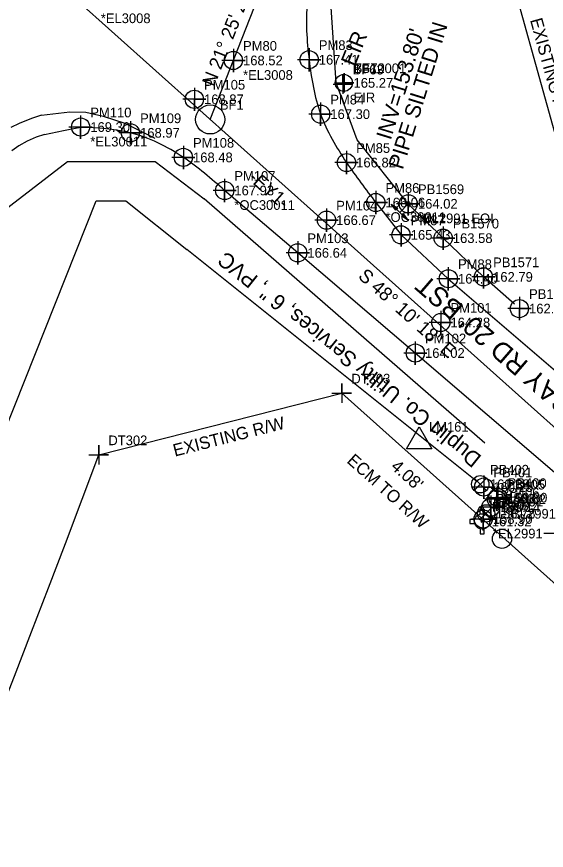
# Model space of a CAD drawing. Extents: x 2262665 to 2270527, y 505476 to 514960.
# Drawn here: x 2266186.8 to 2266323.3, y 509233.9 to 509448.8 of the extents above; entities that cross this region are included whole.
import ezdxf

# ---------------------------------------------------------------- set-up
doc = ezdxf.new("R2010")
doc.units = 0
for name, color, linetype in [('Exist DTM Crownline Cogo Comment', 7, 'Continuous'), ('Exist DTM Crownline Cogo Elevation', 7, 'Continuous'), ('Exist DTM Crownline Cogo Number', 7, 'Continuous'), ('Exist DTM Crownline Cogo Point CELL', 7, 'Continuous'), ('Exist Horizontal Alignment', 7, 'Continuous'), ('Exist Horizontal Alignment Direction Label', 7, 'Continuous'), ('Exist Property Corner CELL', 7, 'Continuous'), ('Exist Property Corner Cogo Number', 7, 'Continuous'), ('Exist Property Iron Pin CELL', 7, 'Continuous'), ('Exist Property Iron Pin Cogo Comment', 7, 'Continuous'), ('Exist Property Iron Pin Cogo Elevation', 7, 'Continuous'), ('Exist Property Iron Pin Cogo Number', 7, 'Continuous'), ('Exist Property Iron Pin Text', 7, 'Continuous'), ('Exist Right of Way Control of Access Line', 7, 'Continuous'), ('Exist Right of Way Line', 7, 'Continuous'), ('Exist Right of Way Line Text', 7, 'Continuous'), ('Exist Right of Way Monument CELL', 7, 'Continuous'), ('Exist Right of Way Monument Cogo Number', 7, 'Continuous'), ('Exist Right of Way Monument Text', 7, 'Continuous'), ('Exist Roads EOP', 7, 'Continuous'), ('Exist Roads EOP Cogo Comment', 7, 'Continuous'), ('Exist Roads EOP Cogo Elevation', 7, 'Continuous'), ('Exist Roads EOP Cogo Number', 7, 'Continuous'), ('Exist Roads EOP Cogo Point CELL', 7, 'Continuous'), ('Exist Roads EOP Text', 7, 'Continuous'), ('Exist Roads EOT', 7, 'Continuous'), ('Exist Structure Minor Pipes RCP 18 Inch Invert', 7, 'Continuous'), ('Exist Survey Centerline Point Cogo Number', 7, 'Continuous'), ('Exist Utilities Other Pole CELL', 7, 'Continuous'), ('Exist Utilities Telephone UG Cable SUE LOS C', 7, 'Continuous'), ('Exist Utilities Water Change of Service SUE CELL', 7, 'Continuous'), ('Exist Utilities Water Fire Hydrant CELL', 7, 'Continuous'), ('Exist Utilities Water Fire Hydrant Cogo Elevation', 7, 'Continuous'), ('Exist Utilities Water Fire Hydrant Cogo Number', 7, 'Continuous'), ('Exist Utilities Water UG Line SUE LOS B', 7, 'Continuous'), ('Exist Utilities Water UG Line SUE LOS B Cogo Comment', 7, 'Continuous'), ('Exist Utilities Water UG Line SUE LOS B Cogo Elevation', 7, 'Continuous'), ('Exist Utilities Water UG Line SUE LOS B Cogo Number', 7, 'Continuous'), ('Exist Utilities Water UG Line SUE LOS B Cogo Point CELL', 7, 'Continuous'), ('Exist Utilities Water UG Line SUE LOS C', 7, 'Continuous'), ('Exist Utilities Water UG Line SUE LOS C Text', 7, 'Continuous'), ('Exist Utilities Water Valve CELL', 7, 'Continuous'), ('Exist Utilities Water Valve Cogo Elevation', 7, 'Continuous'), ('Exist Utilities Water Valve Cogo Number', 7, 'Continuous')]:
    doc.layers.add(name, color=color, linetype=linetype)

msp = doc.modelspace()

# ---------------------------------------------------------------- linework, layer by layer
at = {"layer": 'Exist DTM Crownline Cogo Point CELL'}
for points in [[(2266242.63, 509440.55), (2266242.63, 509434.55), (2266242.63, 509437.55), (2266245.63, 509437.55), (2266239.63, 509437.55)], [(2266232.58, 509430.53), (2266232.58, 509424.53), (2266232.58, 509427.53), (2266235.58, 509427.53), (2266229.58, 509427.53)], [(2266266.63, 509399.37), (2266266.63, 509393.37), (2266266.63, 509396.37), (2266269.63, 509396.37), (2266263.63, 509396.37)], [(2266296.08, 509372.99), (2266296.08, 509366.99), (2266296.08, 509369.99), (2266299.08, 509369.99), (2266293.08, 509369.99)]]:
    msp.add_lwpolyline(points, dxfattribs=at)
for centre in [(2266242.63, 509437.55), (2266232.58, 509427.53), (2266266.63, 509396.37), (2266296.08, 509369.99)]:
    msp.add_circle(centre, 2.34, dxfattribs=at)
at = {"layer": 'Exist Horizontal Alignment'}
for p, q in [((2266236.66, 509422.34), (2266258.08, 509476.92)), ((2266178.94, 509474), (2266399.27, 509276.81))]:
    msp.add_line(p, q, dxfattribs=at)
msp.add_circle((2266236.66, 509422.34), 3.75, dxfattribs=at)
msp.add_arc((2263436.25, 510359.19), 2882, 309.60499, 355.6461, dxfattribs=at)
at = {"layer": 'Exist Property Corner CELL'}
for p, q in [((2266270.88, 509431.44), (2266270.88, 509431.44)), ((2266271.15, 509431.81), (2266271.15, 509431.81)), ((2266270.54, 509351.76), (2266270.54, 509351.76)), ((2266207.93, 509335.86), (2266207.93, 509335.86))]:
    msp.add_line(p, q, dxfattribs=at)
for points in [[(2266268.38, 509431.44), (2266273.38, 509431.44), (2266270.88, 509431.44), (2266270.88, 509433.94), (2266270.88, 509428.94)], [(2266268.65, 509431.81), (2266273.65, 509431.81), (2266271.15, 509431.81), (2266271.15, 509434.31), (2266271.15, 509429.31)], [(2266268.04, 509351.76), (2266273.04, 509351.76), (2266270.54, 509351.76), (2266270.54, 509354.26), (2266270.54, 509349.26)], [(2266205.43, 509335.86), (2266210.43, 509335.86), (2266207.93, 509335.86), (2266207.93, 509338.36), (2266207.93, 509333.36)]]:
    msp.add_lwpolyline(points, dxfattribs=at)
at = {"layer": 'Exist Property Iron Pin CELL'}
for radius in [2.2, 0.0707]:
    msp.add_circle((2266271.1, 509431.77), radius, dxfattribs=at)
at = {"layer": 'Exist Right of Way Control of Access Line'}
msp.add_arc((2263436.25, 510359.19), 2954.56, 309.60499, 339.73535, dxfattribs=at)
at = {"layer": 'Exist Right of Way Line'}
for p, q in [((2266338.62, 509371.34), (2266300.77, 509507.99)), ((2266207.93, 509335.86), (2266270.54, 509351.76)), ((2266270.54, 509351.76), (2266379.26, 509254.45))]:
    msp.add_line(p, q, dxfattribs=at)
at = {"layer": 'Exist Right of Way Monument CELL'}
msp.add_line((2266290.53, 509339.34), (2266290.53, 509339.34), dxfattribs=at)
msp.add_lwpolyline([(2266287.28, 509337.45), (2266290.53, 509343.09), (2266293.78, 509337.45)], close=True, dxfattribs=at)
at = {"layer": 'Exist Roads EOP'}
for points in [[(2266193.93, 509418.46), (2266198.9, 509419.48), (2266203.27, 509420.38)], [(2266193.93, 509418.46), (2266191.83, 509417.73), (2266189.54, 509416.73), (2266187.34, 509415.54), (2266185.52, 509414.28)], [(2266433.99, 509238.04), (2266398.29, 509268.53), (2266362.33, 509299.54), (2266326.58, 509330.27), (2266289.52, 509362.12), (2266259.21, 509387.95), (2266240.39, 509404.02)], [(2266279.33, 509400.92), (2266285.84, 509392.58), (2266298.02, 509381.27), (2266334.05, 509350.29), (2266369.7, 509319.66), (2266406.58, 509288.07), (2266446.43, 509253.76)]]:
    msp.add_lwpolyline(points, dxfattribs=at)
for points in [[(2266265.02, 509466.48), (2266261.73, 509452.49), (2266262.15, 509437.74), (2266265.12, 509423.7), (2266271.79, 509411.22), (2266279.33, 509400.92)], [(2266240.39, 509404.02), (2266229.74, 509412.56), (2266216.1, 509418.89), (2266203.27, 509420.38)]]:
    msp.add_spline(points, degree=3, dxfattribs=at)
at = {"layer": 'Exist Roads EOP Cogo Point CELL'}
for points in [[(2266262.15, 509440.74), (2266262.15, 509434.74), (2266262.15, 509437.74), (2266265.15, 509437.74), (2266259.15, 509437.74)], [(2266265.12, 509426.7), (2266265.12, 509420.7), (2266265.12, 509423.7), (2266268.12, 509423.7), (2266262.12, 509423.7)], [(2266203.27, 509423.38), (2266203.27, 509417.38), (2266203.27, 509420.38), (2266206.27, 509420.38), (2266200.27, 509420.38)], [(2266216.1, 509421.89), (2266216.1, 509415.89), (2266216.1, 509418.89), (2266219.1, 509418.89), (2266213.1, 509418.89)], [(2266229.74, 509415.56), (2266229.74, 509409.56), (2266229.74, 509412.56), (2266232.74, 509412.56), (2266226.74, 509412.56)], [(2266271.79, 509414.22), (2266271.79, 509408.22), (2266271.79, 509411.22), (2266274.79, 509411.22), (2266268.79, 509411.22)], [(2266240.39, 509407.02), (2266240.39, 509401.02), (2266240.39, 509404.02), (2266243.39, 509404.02), (2266237.39, 509404.02)], [(2266279.33, 509403.92), (2266279.33, 509397.92), (2266279.33, 509400.92), (2266282.33, 509400.92), (2266276.33, 509400.92)], [(2266285.84, 509395.58), (2266285.84, 509389.58), (2266285.84, 509392.58), (2266288.84, 509392.58), (2266282.84, 509392.58)], [(2266259.21, 509390.95), (2266259.21, 509384.95), (2266259.21, 509387.95), (2266262.21, 509387.95), (2266256.21, 509387.95)], [(2266298.02, 509384.27), (2266298.02, 509378.27), (2266298.02, 509381.27), (2266301.02, 509381.27), (2266295.02, 509381.27)], [(2266289.52, 509365.12), (2266289.52, 509359.12), (2266289.52, 509362.12), (2266292.52, 509362.12), (2266286.52, 509362.12)]]:
    msp.add_lwpolyline(points, dxfattribs=at)
for centre in [(2266262.15, 509437.74), (2266265.12, 509423.7), (2266203.27, 509420.38), (2266216.1, 509418.89), (2266229.74, 509412.56), (2266271.79, 509411.22), (2266240.39, 509404.02), (2266279.33, 509400.92), (2266285.84, 509392.58), (2266259.21, 509387.95), (2266298.02, 509381.27), (2266289.52, 509362.12)]:
    msp.add_circle(centre, 2.34, dxfattribs=at)
at = {"layer": 'Exist Roads EOT'}
for points in [[(2266193.21, 509423.45), (2266190.85, 509422.63), (2266189.75, 509422.25), (2266187.47, 509421.32), (2266185.32, 509420.24)], [(2266193.21, 509423.45), (2266200.49, 509424.34), (2266204.58, 509424.24), (2266209.09, 509423.18), (2266214.64, 509421.37), (2266222.36, 509417.49), (2266222.36, 509417.49)]]:
    msp.add_lwpolyline(points, dxfattribs=at)
at = {"layer": 'Exist Utilities Other Pole CELL'}
msp.add_circle((2266311.85, 509314.22), 2.46, dxfattribs=at)
at = {"layer": 'Exist Utilities Telephone UG Cable SUE LOS C'}
for points in [[(2266141.08, 509314.55), (2266170.62, 509388.94), (2266199.91, 509411.54), (2266222.49, 509411.54), (2266235.12, 509401.86)], [(2266307.45, 509338.84), (2266235.12, 509401.86), (2266235.12, 509401.86), (2266235.12, 509401.86)]]:
    msp.add_lwpolyline(points, dxfattribs=at)
at = {"layer": 'Exist Utilities Water Change of Service SUE CELL'}
for p, q in [((2266285.57, 509398.36), (2266283.3, 509400.53)), ((2266283.3, 509400.53), (2266287.61, 509396.4)), ((2266287.7, 509400.59), (2266285.57, 509398.36)), ((2266287.7, 509400.59), (2266287.7, 509400.59))]:
    msp.add_line(p, q, dxfattribs=at)
for points in [[(2266283.3, 509400.53), (2266284.97, 509399.41), (2266284.43, 509399.45), (2266284.49, 509398.97)], [(2266287.61, 509396.4), (2266285.95, 509397.52), (2266286.49, 509397.48), (2266286.43, 509397.96)]]:
    msp.add_lwpolyline(points, close=True, dxfattribs=at)
msp.add_circle((2266287.7, 509400.59), 0.517, dxfattribs=at)
at = {"layer": 'Exist Utilities Water Fire Hydrant CELL'}
msp.add_line((2266306.73, 509318.71), (2266306.73, 509318.71), dxfattribs=at)
for points in [[(2266306.21, 509320.62), (2266306.21, 509321.91), (2266307.24, 509321.91), (2266307.24, 509320.6)], [(2266304.81, 509319.23), (2266303.53, 509319.23), (2266303.53, 509318.2), (2266304.81, 509318.2)], [(2266306.21, 509316.8), (2266306.21, 509315.51), (2266307.24, 509315.51), (2266307.24, 509316.83)]]:
    msp.add_lwpolyline(points, dxfattribs=at)
for radius in [1.98, 0.243]:
    msp.add_circle((2266306.73, 509318.71), radius, dxfattribs=at)
at = {"layer": 'Exist Utilities Water UG Line SUE LOS B'}
for points in [[(2266315.06, 509374.69), (2266307.07, 509381.75), (2266296.69, 509391.73), (2266287.7, 509400.59)], [(2266316.33, 509373.57), (2266316.33, 509373.57)]]:
    msp.add_lwpolyline(points, dxfattribs=at)
at = {"layer": 'Exist Utilities Water UG Line SUE LOS B Cogo Point CELL'}
for points in [[(2266287.7, 509403.59), (2266287.7, 509397.59), (2266287.7, 509400.59), (2266290.7, 509400.59), (2266284.7, 509400.59)], [(2266296.69, 509394.73), (2266296.69, 509388.73), (2266296.69, 509391.73), (2266299.69, 509391.73), (2266293.69, 509391.73)], [(2266307.07, 509384.75), (2266307.07, 509378.75), (2266307.07, 509381.75), (2266310.07, 509381.75), (2266304.07, 509381.75)], [(2266316.33, 509376.57), (2266316.33, 509370.57), (2266316.33, 509373.57), (2266319.33, 509373.57), (2266313.33, 509373.57)], [(2266307.13, 509330.57), (2266307.13, 509324.57), (2266307.13, 509327.57), (2266310.13, 509327.57), (2266304.13, 509327.57)], [(2266310.82, 509327.83), (2266310.82, 509321.83), (2266310.82, 509324.83), (2266313.82, 509324.83), (2266307.82, 509324.83)], [(2266310.42, 509327.43), (2266310.42, 509321.43), (2266310.42, 509324.43), (2266313.42, 509324.43), (2266307.42, 509324.43)], [(2266308.96, 509325.36), (2266308.96, 509319.36), (2266308.96, 509322.36), (2266311.96, 509322.36), (2266305.96, 509322.36)], [(2266307.01, 509322.33), (2266307.01, 509316.33), (2266307.01, 509319.33), (2266310.01, 509319.33), (2266304.01, 509319.33)], [(2266325.67, 509318.61), (2266325.67, 509312.61), (2266325.67, 509315.61), (2266328.67, 509315.61), (2266322.67, 509315.61)]]:
    msp.add_lwpolyline(points, dxfattribs=at)
for centre in [(2266287.7, 509400.59), (2266296.69, 509391.73), (2266307.07, 509381.75), (2266316.33, 509373.57), (2266307.13, 509327.57), (2266310.42, 509324.43), (2266310.82, 509324.83), (2266308.96, 509322.36), (2266307.01, 509319.33)]:
    msp.add_circle(centre, 2.34, dxfattribs=at)
at = {"layer": 'Exist Utilities Water UG Line SUE LOS C'}
for points in [[(2266274.51, 509417.09), (2266269.16, 509431.78), (2266267.85, 509451.2), (2266275.52, 509476.49)], [(2266287.7, 509400.59), (2266274.51, 509417.09)], [(2266060.68, 509059.94), (2266102.63, 509144.29), (2266138.79, 509229.27), (2266207.31, 509401.38), (2266214.94, 509401.38), (2266230.6, 509388.77)], [(2266305.36, 509328.98), (2266230.6, 509388.77), (2266230.6, 509388.77), (2266230.6, 509388.77)]]:
    msp.add_lwpolyline(points, dxfattribs=at)
at = {"layer": 'Exist Utilities Water Valve CELL'}
for points in [[(2266307.83, 509329.86), (2266304.68, 509326.71), (2266306.25, 509328.28), (2266307.83, 509326.71), (2266304.68, 509329.86)], [(2266309.33, 509322.36), (2266306.18, 509319.21), (2266307.75, 509320.78), (2266309.33, 509319.21), (2266306.18, 509322.36)]]:
    msp.add_lwpolyline(points, dxfattribs=at)
for centre in [(2266306.25, 509328.28), (2266307.75, 509320.78)]:
    msp.add_circle(centre, 2.23, dxfattribs=at)

# ---------------------------------------------------------------- texts
at = {"layer": 'Exist DTM Crownline Cogo Comment'}
for p in [(2266208.47, 509447.17), (2266245.13, 509432.55)]:
    msp.add_text('*EL3008', height=2.5, dxfattribs=at).set_placement(p)
at = {"layer": 'Exist DTM Crownline Cogo Elevation'}
for s, p in [('168.52', (2266245.13, 509436.3)), ('168.87', (2266235.08, 509426.28)), ('166.67', (2266269.13, 509395.12)), ('164.28', (2266298.58, 509368.74))]:
    msp.add_text(s, height=2.5, dxfattribs=at).set_placement(p)
at = {"layer": 'Exist DTM Crownline Cogo Number'}
for s, p in [('PM80', (2266245.13, 509440.05)), ('PM105', (2266235.08, 509430.03)), ('PM104', (2266269.13, 509398.87)), ('PM101', (2266298.58, 509372.49))]:
    msp.add_text(s, height=2.5, dxfattribs=at).set_placement(p)
at = {"layer": 'Exist Horizontal Alignment Direction Label'}
for s, rotation, p in [('N 21%%d 25\' 27.4" E', 68.4268, (2266237.69, 509430.6)), ('-EY1-', 318.1717, (2266246.28, 509406.95)), ('S 48%%d 10\' 18" E', 318.1717, (2266274.55, 509381.62))]:
    msp.add_text(s, height=3.5, rotation=rotation, dxfattribs=at).set_placement(p)
at = {"layer": 'Exist Property Corner Cogo Number'}
for s, p in [('BF63', (2266273.38, 509433.94)), ('BF72', (2266273.65, 509434.31)), ('DT303', (2266273.04, 509354.26)), ('DT302', (2266210.43, 509338.36))]:
    msp.add_text(s, height=2.5, dxfattribs=at).set_placement(p)
at = {"layer": 'Exist Property Iron Pin Cogo Comment'}
msp.add_text('EIR', height=2.5, dxfattribs=at).set_placement((2266273.6, 509426.77))
at = {"layer": 'Exist Property Iron Pin Cogo Elevation'}
msp.add_text('165.27', height=2.5, dxfattribs=at).set_placement((2266273.6, 509430.52))
at = {"layer": 'Exist Property Iron Pin Cogo Number'}
msp.add_text('TB10001', height=2.5, dxfattribs=at).set_placement((2266273.6, 509434.27))
at = {"layer": 'Exist Property Iron Pin Text'}
msp.add_text('EIR', height=4, rotation=68.031, dxfattribs=at).set_placement((2266273.91, 509435.8))
at = {"layer": 'Exist Right of Way Line Text'}
for rotation, p in [(285.4855, (2266319.05, 509447.99)), (14.2856, (2266227.55, 509335.4))]:
    msp.add_text('EXISTING R/W', height=3.2, rotation=rotation, dxfattribs=at).set_placement(p)
at = {"layer": 'Exist Right of Way Monument Cogo Number'}
msp.add_text('LM161', height=2.5, dxfattribs=at).set_placement((2266293.03, 509341.84))
at = {"layer": 'Exist Right of Way Monument Text'}
for s, p in [('ECM TO R/W', (2266271.67, 509334.05)), (" 4.08' ", (2266282.09, 509333.31))]:
    msp.add_text(s, height=3.2, rotation=318.1717, dxfattribs=at).set_placement(p)
at = {"layer": 'Exist Roads EOP Cogo Comment'}
for s, p in [('*EL30011', (2266205.77, 509415.38)), ('*OC30011', (2266242.89, 509399.02)), ('*OC30011', (2266281.83, 509395.92))]:
    msp.add_text(s, height=2.5, dxfattribs=at).set_placement(p)
at = {"layer": 'Exist Roads EOP Cogo Elevation'}
for s, p in [('167.41', (2266264.65, 509436.49)), ('167.30', (2266267.62, 509422.45)), ('169.30', (2266205.77, 509419.13)), ('168.97', (2266218.6, 509417.64)), ('168.48', (2266232.24, 509411.31)), ('166.82', (2266274.29, 509409.97)), ('167.93', (2266242.89, 509402.77)), ('166.06', (2266281.83, 509399.67)), ('165.43', (2266288.34, 509391.33)), ('166.64', (2266261.71, 509386.7)), ('164.40', (2266300.52, 509380.02)), ('164.02', (2266292.02, 509360.87))]:
    msp.add_text(s, height=2.5, dxfattribs=at).set_placement(p)
at = {"layer": 'Exist Roads EOP Cogo Number'}
for s, p in [('PM83', (2266264.65, 509440.24)), ('PM84', (2266267.62, 509426.2)), ('PM110', (2266205.77, 509422.88)), ('PM109', (2266218.6, 509421.39)), ('PM108', (2266232.24, 509415.06)), ('PM85', (2266274.29, 509413.72)), ('PM107', (2266242.89, 509406.52)), ('PM86', (2266281.83, 509403.42)), ('PM87', (2266288.34, 509395.08)), ('PM103', (2266261.71, 509390.45)), ('PM88', (2266300.52, 509383.77)), ('PM102', (2266292.02, 509364.62))]:
    msp.add_text(s, height=2.5, dxfattribs=at).set_placement(p)
at = {"layer": 'Exist Roads EOP Text'}
msp.add_text("SR 1320 EDWINA KORNEGAY RD 20' BST", height=5, rotation=139.146, dxfattribs=at).set_placement((2266391.71, 509296.69))
at = {"layer": 'Exist Structure Minor Pipes RCP 18 Inch Invert'}
for s, p in [('PIPE SILTED IN', (2266286.27, 509409.22)), ("INV=153.80'", (2266283.17, 509416.84))]:
    msp.add_text(s, height=4, rotation=72.7638, dxfattribs=at).set_placement(p)
at = {"layer": 'Exist Survey Centerline Point Cogo Number'}
msp.add_text('BF1', height=2.5, dxfattribs=at).set_placement((2266239.16, 509424.84))
at = {"layer": 'Exist Utilities Water Fire Hydrant Cogo Elevation'}
msp.add_text('161.32', height=2.5, dxfattribs=at).set_placement((2266309.23, 509317.46))
at = {"layer": 'Exist Utilities Water Fire Hydrant Cogo Number'}
msp.add_text('PB408', height=2.5, dxfattribs=at).set_placement((2266309.23, 509321.21))
at = {"layer": 'Exist Utilities Water UG Line SUE LOS B Cogo Comment'}
for s, p in [('*BL2991 EOI', (2266290.2, 509395.59)), ('*EL2991', (2266309.63, 509322.57)), ('*BL2991', (2266312.92, 509319.43)), ('T', (2266313.32, 509319.83)), ('*EL2991', (2266309.51, 509314.33))]:
    msp.add_text(s, height=2.5, dxfattribs=at).set_placement(p)
at = {"layer": 'Exist Utilities Water UG Line SUE LOS B Cogo Elevation'}
for s, p in [('164.02', (2266290.2, 509399.34)), ('163.58', (2266299.19, 509390.48)), ('162.79', (2266309.57, 509380.5)), ('162.40', (2266318.83, 509372.32)), ('160.25', (2266309.63, 509326.32)), ('159.62', (2266312.92, 509323.18)), ('159.80', (2266313.32, 509323.58)), ('159.14', (2266311.46, 509321.11)), ('158.90', (2266309.51, 509318.08))]:
    msp.add_text(s, height=2.5, dxfattribs=at).set_placement(p)
at = {"layer": 'Exist Utilities Water UG Line SUE LOS B Cogo Number'}
for s, p in [('PB1569', (2266290.2, 509403.09)), ('PB1570', (2266299.19, 509394.23)), ('PB1571', (2266309.57, 509384.25)), ('PB1572', (2266318.83, 509376.07)), ('PB401', (2266309.63, 509330.07)), ('PB405', (2266312.92, 509326.93)), ('PB400', (2266313.32, 509327.33)), ('PB406', (2266311.46, 509324.86)), ('PB407', (2266309.51, 509321.83))]:
    msp.add_text(s, height=2.5, dxfattribs=at).set_placement(p)
at = {"layer": 'Exist Utilities Water UG Line SUE LOS C Text'}
msp.add_text('Duplin Co. Utility Services, 6 ", PVC', height=4, rotation=141.229, dxfattribs=at).set_placement((2266306.84, 509335.42))
at = {"layer": 'Exist Utilities Water Valve Cogo Elevation'}
for s, p in [('160.38', (2266308.75, 509327.03)), ('158.78', (2266310.25, 509319.53))]:
    msp.add_text(s, height=2.5, dxfattribs=at).set_placement(p)
at = {"layer": 'Exist Utilities Water Valve Cogo Number'}
for s, p in [('PB402', (2266308.75, 509330.78)), ('PB403', (2266310.25, 509323.28))]:
    msp.add_text(s, height=2.5, dxfattribs=at).set_placement(p)

doc.saveas('drawing.dxf')
